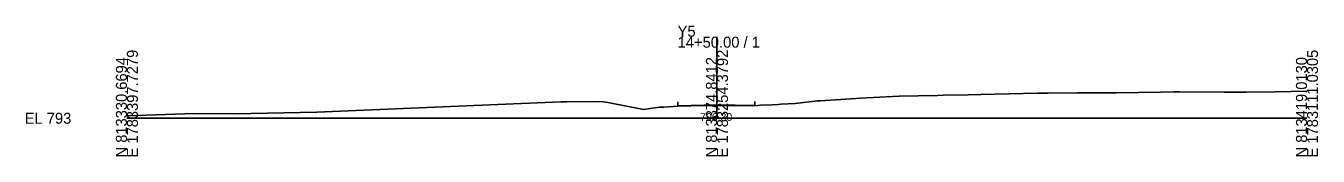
# Model space of a CAD drawing. Extents: x -26 to 1603, y -10 to 6526.
# Drawn here: x 1274.3 to 1602.8, y 1490.3 to 1523.6 of the extents above; entities that cross this region are included whole.
import ezdxf

# ---------------------------------------------------------------- set-up
doc = ezdxf.new("R2010")
doc.units = 0
for name, color, linetype in [('Exist Cross Section Cell', 7, 'Continuous'), ('Exist XS Center Line Elevation Label', 7, 'Continuous'), ('Exist XS Ground Line', 7, 'Continuous'), ('Prop XS EOT Tick Mark', 7, 'Continuous'), ('Prop XS Finish Grade Pavement', 7, 'Continuous')]:
    doc.layers.add(name, color=color, linetype=linetype)

msp = doc.modelspace()

# ---------------------------------------------------------------- linework, layer by layer
at = {"layer": 'Exist Cross Section Cell'}
for p, q in [((1450, 1500), (1450, 1520.81)), ((1300, 1500), (1450, 1500)), ((1450, 1500), (1600, 1500))]:
    msp.add_line(p, q, dxfattribs=at)
at = {"layer": 'Exist XS Ground Line'}
for p, q in [((1476.25, 1504.47), (1485.41, 1505.08)), ((1485.41, 1505.08), (1486.49, 1505.13)), ((1486.49, 1505.13), (1496.3, 1505.6)), ((1496.3, 1505.6), (1506, 1505.83)), ((1506, 1505.83), (1507.51, 1505.86)), ((1507.51, 1505.86), (1513.87, 1505.96)), ((1513.87, 1505.96), (1517.1, 1506.06)), ((1517.1, 1506.06), (1531.47, 1506.38)), ((1531.47, 1506.38), (1534.19, 1506.4)), ((1534.19, 1506.4), (1541.56, 1506.46)), ((1541.56, 1506.46), (1551.49, 1506.51)), ((1551.49, 1506.51), (1562.8, 1506.68)), ((1562.8, 1506.68), (1566.17, 1506.71)), ((1566.17, 1506.71), (1567.62, 1506.71)), ((1567.62, 1506.71), (1578.96, 1506.65)), ((1578.96, 1506.65), (1584.56, 1506.67)), ((1584.56, 1506.67), (1591.91, 1506.77)), ((1591.91, 1506.77), (1600, 1506.94)), ((1327.38, 1501.15), (1348.29, 1501.53)), ((1348.29, 1501.53), (1410.29, 1504.19)), ((1410.29, 1504.19), (1411.08, 1504.21)), ((1411.08, 1504.21), (1411.75, 1504.23)), ((1411.75, 1504.23), (1419.79, 1504.24)), ((1419.79, 1504.24), (1421.15, 1504.22)), ((1421.15, 1504.22), (1421.61, 1504.12)), ((1421.61, 1504.12), (1422.3, 1504.02)), ((1422.3, 1504.02), (1431.33, 1502.26)), ((1431.33, 1502.26), (1434.22, 1502.65)), ((1434.22, 1502.65), (1435.45, 1502.83)), ((1435.45, 1502.83), (1436.52, 1502.87)), ((1436.52, 1502.87), (1440.02, 1503.08)), ((1440.02, 1503.08), (1446.76, 1503.23)), ((1446.76, 1503.23), (1449.77, 1503.3)), ((1449.77, 1503.3), (1454.67, 1503.25)), ((1454.67, 1503.25), (1459.65, 1503.17)), ((1459.65, 1503.17), (1461.09, 1503.37)), ((1461.09, 1503.37), (1464.02, 1503.44)), ((1464.02, 1503.44), (1465.55, 1503.55)), ((1465.55, 1503.55), (1466.21, 1503.57)), ((1466.21, 1503.57), (1469.89, 1503.75)), ((1469.89, 1503.75), (1475.6, 1504.42)), ((1475.6, 1504.42), (1476.25, 1504.47)), ((1300, 1500.63), (1317.15, 1501.18)), ((1317.15, 1501.18), (1327.38, 1501.15))]:
    msp.add_line(p, q, dxfattribs=at)
at = {"layer": 'Prop XS EOT Tick Mark'}
for p, q in [((1440.02, 1503.21), (1440.02, 1504.21)), ((1459.65, 1503.29), (1459.65, 1504.29))]:
    msp.add_line(p, q, dxfattribs=at)
at = {"layer": 'Prop XS Finish Grade Pavement'}
for p, q in [((1440.02, 1503.21), (1446.76, 1503.36)), ((1446.76, 1503.36), (1449.77, 1503.43)), ((1449.77, 1503.43), (1454.67, 1503.37)), ((1454.67, 1503.37), (1459.65, 1503.29))]:
    msp.add_line(p, q, dxfattribs=at)

# ---------------------------------------------------------------- texts
at = {"layer": 'Exist Cross Section Cell'}
for s, p in [('Y5', (1440, 1520.81)), ('14+50.00 / 1', (1440, 1518.01)), ('EL 793', (1274, 1498.6))]:
    msp.add_text(s, height=2.8, dxfattribs=at).set_placement(p)
for s, p in [('N 813330.6694', (1300, 1490)), ('E 1783397.7279', (1302.8, 1490)), ('N 813374.8412', (1450, 1490)), ('E 1783254.3792', (1452.8, 1490)), ('N 813419.0130', (1600, 1490)), ('E 1783111.0305', (1602.8, 1490))]:
    msp.add_text(s, height=2.8, rotation=90, dxfattribs=at).set_placement(p)
at = {"layer": 'Exist XS Center Line Elevation Label'}
msp.add_text('796.30', height=2, dxfattribs=at).set_placement((1445.71, 1499.3))

doc.saveas('drawing.dxf')
